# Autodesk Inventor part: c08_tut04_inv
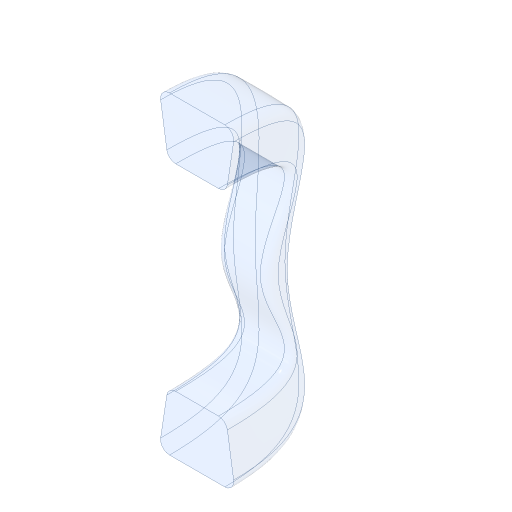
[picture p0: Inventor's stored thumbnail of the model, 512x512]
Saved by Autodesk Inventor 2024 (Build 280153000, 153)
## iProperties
Created: 2015-03
Part Number: c08_tut04_inv
Material: Generic
Document SubType Name: Modeling
Designer: Sandeep
Density: 1 g/cm^3
Appearance: Blue - Glazing
Mass: 996.637 g
Surface Area: 881.078 cm^2
Volume: 996.637 cm^3
Author: Sandeep
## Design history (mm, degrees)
sketch "Sketch1"
  geometry: L1 (-20, 50.541)-(20, 50.541); L2 (30, 60.541)-(30, 70.541); L3 (-30, 60.541)-(-30, 70.541); L4 (0, -9.695)-(0, 120.745); L5 (0, 82)-(-105.666, 82); A1 r 45 centre (0, 37) between (30, 70.541) and (-30, 70.541); A2 r 10 centre (-20, 60.541) between (-30, 60.541) and (-20, 50.541); A3 r 10 centre (20, 60.541) between (20, 50.541) and (30, 60.541); 2 further points
  constraints: 10 end point, 7 point on circle, 5 point on line, 4 tangent, 3 centre point, 2 horizontal, 2 vertical, 1 perpendicular, 1 other
  dimensions: "d0" = 60 distance between parallel lines of L2 L3; "d2" = 20 distance of point (30, 50.541) L2.end; "d3" = 45 radius of A1; "d4" = 10 radius of A2; "d5" = 10 radius of A3; "d22" = 82 distance from line of point (0, 0) L5
sketch "Sketch2"
  geometry: L1 (30.844, 175)-(-30.844, 175); L2 (-40.728, 163.479)-(-33.805, 118.479); L3 (-23.921, 110)-(23.921, 110); L4 (33.805, 118.479)-(40.728, 163.479); L5 (0, 0)-(0, 325.346); A1 r 10 centre (30.844, 165) between (40.728, 163.479) and (30.844, 175); A2 r 10 centre (-30.844, 165) between (-30.844, 175) and (-40.728, 163.479); A3 r 10 centre (-23.921, 120) between (-33.805, 118.479) and (-23.921, 110); A4 r 10 centre (23.921, 120) between (23.921, 110) and (33.805, 118.479); 4 further points
  constraints: 10 end point, 8 point on circle, 8 point on line, 8 tangent, 4 centre point, 3 equal radius, 1 horizontal, 1 parallel, 1 vertical, 1 other
  dimensions: "d6" = 65 distance of point (-32.5, 110) point (32.5, 110); "d7" = 65 distance between parallel lines of L1 L3; "d8" = 85 distance of point (42.5, 175) point (-42.5, 175); "d9" = 175 distance from line of L5.start L1; "d10" = 10 radius of A1
loft "Loft2" sketch "Sketch1", "Sketch2" dims "d23" = 50, "d24" = 90 deg, "d25" = 0, "d26" = 90 deg, "d27" = 50, "d28" = 90 deg
body "Solid2"
sketch "Sketch3"
  geometry: L1 (23.921, -110)-(-23.921, -110); L2 (-33.805, -118.479)-(-40.728, -163.479); L3 (-30.844, -175)-(30.844, -175); L4 (40.728, -163.479)-(33.805, -118.479); L5 (0, 0)-(0, -235.653); A1 r 10 centre (-30.844, -165) between (-40.728, -163.479) and (-30.844, -175); A2 r 10 centre (30.844, -165) between (30.844, -175) and (40.728, -163.479); A3 r 10 centre (23.921, -120) between (33.805, -118.479) and (23.921, -110); A4 r 10 centre (-23.921, -120) between (-23.921, -110) and (-33.805, -118.479); 4 further points
  constraints: 10 end point, 8 point on circle, 8 point on line, 8 tangent, 4 centre point, 3 equal radius, 1 horizontal, 1 parallel, 1 vertical, 1 other
  dimensions: "d11" = 65 distance of point (32.5, -110) point (-32.5, -110); "d12" = 85 distance of point (-42.5, -175) point (42.5, -175); "d13" = 65 distance between parallel lines of L1 L3; "d14" = 175 distance from line of L5.start L3; "d15" = 10 radius of A1
